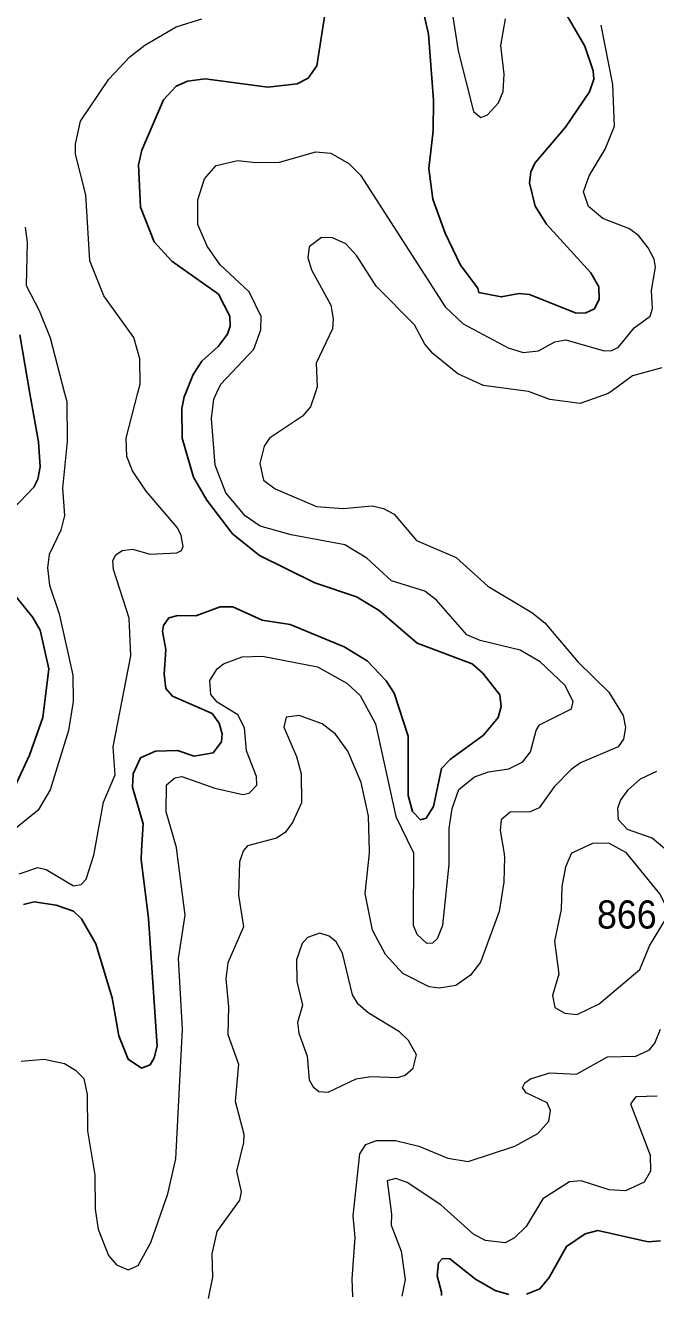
# Model space of a CAD drawing. Extents: x 473.9 to 500, y 7733.1 to 7760.8.
# Drawn here: x 496.397 to 498.186, y 7739.801 to 7743.401 of the extents above; entities that cross this region are included whole.
import ezdxf

# ---------------------------------------------------------------- set-up
doc = ezdxf.new("R2010")
doc.units = 0
doc.header["$LTSCALE"] = 0.032
doc.layers.add('1', color=7, linetype='Continuous', lineweight=25)
doc.layers.add('2', color=7, linetype='Continuous', lineweight=13)
doc.layers.add('21', color=7, linetype='Continuous')

msp = doc.modelspace()

# ---------------------------------------------------------------- linework, layer by layer
at = {"layer": '1'}
for points in [[(497.8918, 7743.5046), (497.9852, 7743.3428), (498.0087, 7743.272), (498.0104, 7743.249), (497.9988, 7743.213), (497.9304, 7743.112)], [(497.2476, 7743.4377), (497.2241, 7743.2861), (497.1996, 7743.2511), (497.1683, 7743.2354), (497.0852, 7743.2257), (496.9077, 7743.2496), (496.8576, 7743.2432), (496.8254, 7743.2288), (496.7893, 7743.1899), (496.7276, 7743.0471), (496.7185, 7743.0052), (496.7237, 7742.885), (496.7626, 7742.7874), (496.8129, 7742.732), (496.9455, 7742.6383), (496.977, 7742.5762), (496.9783, 7742.5475), (496.9708, 7742.5246), (496.9447, 7742.4894), (496.8978, 7742.448), (496.8729, 7742.4108), (496.8522, 7742.3587), (496.8477, 7742.3473), (496.8415, 7742.3136), (496.8423, 7742.2294), (496.8747, 7742.1189), (496.9117, 7742.0536), (496.9851, 7741.958), (497.062, 7741.8961), (497.2183, 7741.8191), (497.3373, 7741.7796), (497.401, 7741.7405), (497.5088, 7741.6474), (497.6658, 7741.5886), (497.6961, 7741.5621), (497.7437, 7741.5013), (497.7474, 7741.4682), (497.7392, 7741.4364), (497.6973, 7741.3867), (497.6039, 7741.3185), (497.578, 7741.2922), (497.5554, 7741.1843), (497.5345, 7741.1512), (497.5186, 7741.1466), (497.4959, 7741.17), (497.4833, 7741.215), (497.4838, 7741.3836), (497.4438, 7741.5054), (497.4209, 7741.5409), (497.3669, 7741.5977), (497.3019, 7741.6369), (497.1486, 7741.7011), (497.0688, 7741.7134), (496.9862, 7741.7509), (496.9502, 7741.7508), (496.8806, 7741.7256), (496.8302, 7741.7261), (496.8045, 7741.7196), (496.7895, 7741.6977), (496.786, 7741.6806), (496.7955, 7741.6296), (496.7908, 7741.5599), (496.7956, 7741.5192), (496.8145, 7741.4968), (496.9275, 7741.4483)], [(497.9304, 7743.112), (497.8433, 7743.0101), (497.8318, 7742.9855), (497.828, 7742.9546), (497.8444, 7742.8884), (497.8766, 7742.8367), (498.002, 7742.6985), (498.0251, 7742.6594), (498.0263, 7742.6244), (498.0123, 7742.5966), (497.9883, 7742.5854), (497.9604, 7742.5847), (497.8283, 7742.6375), (497.7989, 7742.6402), (497.7479, 7742.6307), (497.6842, 7742.6428), (497.6814, 7742.6552), (497.6325, 7742.7203), (497.5887, 7742.8112), (497.5535, 7742.9084), (497.5426, 7742.9948), (497.5547, 7743.1017), (497.5554, 7743.1891), (497.5413, 7743.3765), (497.525, 7743.4473)], [(496.3185, 7741.9843), (496.4214, 7742.0908), (496.4323, 7742.1137), (496.4386, 7742.1484), (496.4342, 7742.2195), (496.4101, 7742.3567), (496.3808, 7742.5231)], [(496.3542, 7741.2116), (496.4091, 7741.3295), (496.4461, 7741.4363), (496.4636, 7741.5749), (496.4394, 7741.6842), (496.4177, 7741.7208), (496.3434, 7741.8135)], [(496.9275, 7741.4483), (496.9472, 7741.4205), (496.9555, 7741.3903), (496.9534, 7741.3672), (496.9302, 7741.3365), (496.8757, 7741.3265), (496.8289, 7741.3426), (496.7661, 7741.3416), (496.7241, 7741.3223), (496.7034, 7741.2771), (496.701, 7741.2392), (496.7311, 7741.135), (496.7271, 7741.0601), (496.7257, 7741.0333), (496.7465, 7740.8658), (496.7707, 7740.504), (496.7628, 7740.4708), (496.751, 7740.4509), (496.7269, 7740.4414), (496.6885, 7740.4672), (496.6625, 7740.5333), (496.6435, 7740.6413), (496.5967, 7740.794), (496.5559, 7740.8652), (496.534, 7740.8867), (496.4844, 7740.9044), (496.4217, 7740.9131), (496.3913, 7740.9056)], [(498.1997, 7739.9512), (498.1651, 7739.9485), (498.0218, 7739.9804), (497.9859, 7739.9712), (497.9329, 7739.9352), (497.8837, 7739.8469), (497.8576, 7739.815), (497.8194, 7739.7995)], [(497.7699, 7739.7987), (497.7311, 7739.81), (497.6752, 7739.8425), (497.6015, 7739.9004), (497.5807, 7739.9007), (497.5698, 7739.8885), (497.5657, 7739.8517), (497.5779, 7739.8059), (497.5781, 7739.7957)]]:
    msp.add_lwpolyline(points, dxfattribs=at)
at = {"layer": '2'}
for points in [[(497.5986, 7743.505), (497.6257, 7743.3291), (497.6689, 7743.1573), (497.69, 7743.1399), (497.7088, 7743.1472), (497.7398, 7743.1812), (497.7532, 7743.2141), (497.7564, 7743.2624), (497.7467, 7743.3444), (497.7597, 7743.4199)], [(496.4324, 7741.0112), (496.4556, 7741.0056), (496.5338, 7740.9585), (496.555, 7740.9631), (496.5696, 7740.9776), (496.5914, 7741.046), (496.5941, 7741.0607), (496.6186, 7741.1963), (496.6515, 7741.2737), (496.6462, 7741.3533), (496.6959, 7741.612), (496.6914, 7741.719), (496.6469, 7741.8567), (496.6454, 7741.882), (496.6542, 7741.8986), (496.6713, 7741.9104), (496.7015, 7741.9141), (496.7515, 7741.9007), (496.8272, 7741.9039), (496.8404, 7741.9111), (496.8446, 7741.9224), (496.8394, 7741.9532), (496.8286, 7741.9747), (496.7399, 7742.079), (496.7007, 7742.137), (496.6848, 7742.1774), (496.6834, 7742.2295), (496.7161, 7742.3581), (496.7224, 7742.3828), (496.7217, 7742.4549), (496.7047, 7742.5156), (496.6193, 7742.6336), (496.5797, 7742.7332), (496.5689, 7742.9204), (496.5395, 7743.0354), (496.5392, 7743.064), (496.5538, 7743.1297), (496.6341, 7743.2489), (496.6939, 7743.312), (496.7362, 7743.3454), (496.8253, 7743.3976), (496.8983, 7743.4202)], [(498.0405, 7742.4772), (498.0623, 7742.4783), (498.0811, 7742.4876), (498.1256, 7742.5432), (498.1709, 7742.5763), (498.1777, 7742.5977), (498.1746, 7742.6486), (498.1857, 7742.715), (498.1817, 7742.7375), (498.1654, 7742.7702), (498.1384, 7742.8042), (498.1124, 7742.8241), (498.0363, 7742.8527), (497.9952, 7742.8871), (497.9818, 7742.9288), (497.9971, 7742.9745), (498.0431, 7743.0504), (498.0693, 7743.1157), (498.0649, 7743.2335), (498.0319, 7743.4018)], [(496.6886, 7739.8689), (496.717, 7739.8811), (496.7532, 7739.9466), (496.801, 7740.0845), (496.8245, 7740.184), (496.8431, 7740.5516), (496.8319, 7740.7528), (496.8503, 7740.876), (496.827, 7741.0596), (496.826, 7741.0674), (496.7963, 7741.1693), (496.7975, 7741.2454), (496.8216, 7741.2658), (496.8415, 7741.2694), (496.9348, 7741.2365), (497.014, 7741.218), (497.0327, 7741.2221), (497.0538, 7741.2443), (497.0535, 7741.2693), (497.0243, 7741.3417), (497.0186, 7741.4075), (497.0004, 7741.4447), (496.9412, 7741.4801), (496.9237, 7741.5021), (496.9205, 7741.5415), (496.9411, 7741.5748), (496.9599, 7741.5893), (497.0124, 7741.6092), (497.0698, 7741.6111), (497.2262, 7741.5809), (497.3095, 7741.5342), (497.3475, 7741.499), (497.3908, 7741.4185), (497.4487, 7741.1554), (497.4973, 7741.0565), (497.4988, 7741.0535), (497.4982, 7740.8471), (497.5081, 7740.8217), (497.5359, 7740.7959), (497.5536, 7740.7968), (497.5665, 7740.8093), (497.5825, 7740.8476), (497.6004, 7741.0197), (497.6002, 7741.056), (497.5997, 7741.1215), (497.6086, 7741.1784), (497.6275, 7741.2319), (497.6721, 7741.268), (497.7119, 7741.282), (497.7699, 7741.2906), (497.809, 7741.3104), (497.8307, 7741.3395), (497.8466, 7741.4), (497.8563, 7741.4156), (497.9476, 7741.4617), (497.9522, 7741.4824), (497.9288, 7741.5288), (497.8583, 7741.5951), (497.8015, 7741.628), (497.6876, 7741.6554), (497.6506, 7741.671), (497.5642, 7741.7695), (497.531, 7741.7957), (497.4364, 7741.8243), (497.3659, 7741.8889), (497.3035, 7741.9268), (497.1519, 7741.9549), (497.0638, 7741.98), (497.0208, 7742.009), (496.9657, 7742.0746), (496.9358, 7742.1533), (496.9251, 7742.2853), (496.9322, 7742.3405), (496.9407, 7742.3591), (496.9517, 7742.3832), (497.0458, 7742.4821), (497.0656, 7742.5376), (497.0659, 7742.575), (497.0324, 7742.6454), (496.9504, 7742.7221), (496.9128, 7742.7751), (496.887, 7742.8365), (496.8866, 7742.9063), (496.9055, 7742.9654), (496.9386, 7743.0039), (497, 7743.018), (497.051, 7743.0118), (497.118, 7743.0134), (497.2215, 7743.0423), (497.2645, 7743.0383), (497.3155, 7743.0097), (497.3482, 7742.9764), (497.5889, 7742.6021), (497.6401, 7742.554), (497.7678, 7742.4859), (497.8105, 7742.4724), (497.8535, 7742.4772), (497.8996, 7742.5035), (497.9317, 7742.5092), (498.0405, 7742.4772)], [(496.3961, 7742.8284), (496.4025, 7742.7857), (496.3992, 7742.6632), (496.4364, 7742.5923), (496.4671, 7742.5145), (496.5083, 7742.3571), (496.5144, 7742.3337), (496.5158, 7742.2198), (496.5022, 7742.0875), (496.5085, 7742.0097), (496.4973, 7741.9689), (496.4647, 7741.8996), (496.4595, 7741.8615), (496.4658, 7741.8119), (496.4928, 7741.7314), (496.5321, 7741.5572), (496.5327, 7741.4823), (496.5198, 7741.3998), (496.4669, 7741.2314), (496.4334, 7741.1741), (496.3293, 7741.0899)], [(498.2034, 7742.4289), (498.1209, 7742.4061), (498.0631, 7742.3643), (498.0518, 7742.3561), (497.9719, 7742.3276), (497.8856, 7742.3394), (497.8256, 7742.3621), (497.8176, 7742.3631), (497.698, 7742.3787), (497.625, 7742.4124), (497.5535, 7742.4703), (497.5312, 7742.4962), (497.5019, 7742.5515), (497.3926, 7742.6615), (497.3383, 7742.7472), (497.3064, 7742.7812), (497.2692, 7742.7986), (497.2373, 7742.7994), (497.2027, 7742.773), (497.1985, 7742.7414), (497.2095, 7742.7076), (497.2637, 7742.6068), (497.2708, 7742.5687), (497.2687, 7742.5398), (497.2221, 7742.4428), (497.2257, 7742.3753), (497.2207, 7742.3604), (497.2066, 7742.3184), (497.1836, 7742.2919), (497.09, 7742.2293), (497.0752, 7742.2068), (497.0627, 7742.1576), (497.0734, 7742.1107), (497.106, 7742.0856), (497.2236, 7742.0354), (497.2992, 7742.0301), (497.3817, 7742.0379), (497.4139, 7742.0302), (497.4439, 7742.0142), (497.5069, 7741.9392), (497.6197, 7741.8907), (497.7098, 7741.8091), (497.8346, 7741.7351), (497.8712, 7741.7053), (497.9649, 7741.595), (498.0534, 7741.5085), (498.0939, 7741.442), (498.1011, 7741.4083), (498.0949, 7741.375), (498.0797, 7741.3531), (497.9731, 7741.3077), (497.9466, 7741.2893), (497.8978, 7741.2397), (497.8558, 7741.1804), (497.8304, 7741.169), (497.7732, 7741.1683), (497.7474, 7741.1465), (497.7448, 7741.1161), (497.7548, 7741.0553), (497.7571, 7741.0411), (497.7548, 7740.9693), (497.7418, 7740.886), (497.6888, 7740.7419), (497.6603, 7740.7054), (497.6191, 7740.6764), (497.572, 7740.6681), (497.5437, 7740.6723), (497.4682, 7740.7102), (497.4197, 7740.7644), (497.3822, 7740.8326), (497.3617, 7740.9371), (497.3737, 7741.0518), (497.3735, 7741.0571), (497.3706, 7741.1563), (497.3499, 7741.2521), (497.3128, 7741.3413), (497.2772, 7741.3892), (497.2392, 7741.4187), (497.1738, 7741.4423), (497.1375, 7741.4374), (497.1307, 7741.4088), (497.1668, 7741.3263), (497.1799, 7741.2769), (497.1807, 7741.1944), (497.1556, 7741.1387)], [(498.2248, 7741.0532), (498.1767, 7741.0939), (498.106, 7741.1188), (498.0808, 7741.1466), (498.0787, 7741.1794), (498.0863, 7741.2008), (498.1085, 7741.2316), (498.1428, 7741.2625), (498.1895, 7741.2841)], [(497.1556, 7741.1387), (497.1341, 7741.1103), (497.1095, 7741.094), (497.0278, 7741.0725), (497.0166, 7741.0587), (497.0151, 7741.0569), (497.0045, 7741.0272), (497.0023, 7740.9322), (497.016, 7740.8423), (496.9718, 7740.7404), (496.966, 7740.6948), (496.9733, 7740.6155), (496.9718, 7740.5371), (497.0022, 7740.4525), (496.9928, 7740.3475), (497.0167, 7740.2542), (497.0165, 7740.2301), (496.9967, 7740.1492), (497.0094, 7740.0906), (497.0053, 7740.0668), (496.9401, 7739.9772), (496.9265, 7739.9143), (496.9283, 7739.8479), (496.9161, 7739.7874)], [(496.3789, 7740.9931), (496.4324, 7741.0112)], [(497.3265, 7739.7925), (497.3246, 7739.8436), (497.3336, 7739.9605), (497.328, 7740.0224), (497.3466, 7740.1985), (497.3632, 7740.2244), (497.3936, 7740.2355), (497.4476, 7740.2364), (497.5136, 7740.2202), (497.5967, 7740.1858), (497.654, 7740.176), (497.7869, 7740.2196), (497.8514, 7740.2554), (497.8829, 7740.2906), (497.8882, 7740.3207), (497.8781, 7740.3433), (497.819, 7740.3715), (497.8081, 7740.3862), (497.8145, 7740.3997), (497.8309, 7740.411), (497.8859, 7740.4283), (497.9612, 7740.4242), (498.0499, 7740.4734), (498.13, 7740.475), (498.1684, 7740.4938), (498.1843, 7740.5126), (498.2, 7740.5517)], [(496.3854, 7740.4615), (496.4501, 7740.467), (496.5082, 7740.4544), (496.5397, 7740.4356), (496.5629, 7740.4116), (496.5728, 7740.3663), (496.573, 7740.2634), (496.5939, 7740.1384), (496.5947, 7740.0414), (496.6036, 7739.9841), (496.6325, 7739.9091), (496.6555, 7739.883), (496.6886, 7739.8689)], [(498.1905, 7740.3618), (498.1302, 7740.3601), (498.1151, 7740.3404), (498.1702, 7740.1948), (498.172, 7740.1493), (498.1537, 7740.1173), (498.1008, 7740.0932), (498.054, 7740.096), (497.9751, 7740.1213), (497.9419, 7740.119), (497.8658, 7740.0706), (497.819, 7739.9921), (497.7857, 7739.9595), (497.7587, 7739.9456), (497.7034, 7739.952), (497.6699, 7739.9695), (497.5763, 7740.0537), (497.4806, 7740.1172), (497.4483, 7740.1284), (497.4239, 7740.1217), (497.4363, 7740.027), (497.435, 7739.9955), (497.4634, 7739.9215), (497.475, 7739.8415), (497.4657, 7739.7943)]]:
    msp.add_lwpolyline(points, dxfattribs=at)
for points in [[(498.1687, 7740.7886), (498.2144, 7740.8633), (498.2155, 7740.9032), (498.1985, 7740.9365), (498.1024, 7741.0534), (498.1018, 7741.0537), (498.0533, 7741.0802), (498.007, 7741.0795), (497.9539, 7741.0544), (497.9478, 7741.0515), (497.93, 7741.0132), (497.9197, 7740.957), (497.9181, 7740.8921), (497.8994, 7740.8021), (497.9115, 7740.7082), (497.8936, 7740.6477), (497.9003, 7740.6137), (497.9286, 7740.5973), (497.9632, 7740.5933), (498.0259, 7740.6238), (498.1409, 7740.7218)], [(497.3697, 7740.5984), (497.3416, 7740.6231), (497.3257, 7740.6498), (497.2973, 7740.7677), (497.2792, 7740.7995), (497.2598, 7740.8161), (497.2325, 7740.8248), (497.1977, 7740.8118), (497.1829, 7740.7953), (497.1664, 7740.749), (497.168, 7740.687), (497.1838, 7740.6204), (497.1697, 7740.5707), (497.1733, 7740.5405), (497.1966, 7740.4755), (497.203, 7740.4086), (497.2136, 7740.3884), (497.2305, 7740.3751), (497.2569, 7740.373), (497.3362, 7740.4114), (497.378, 7740.4178), (497.454, 7740.4144), (497.4754, 7740.4215), (497.498, 7740.4413), (497.5071, 7740.4794), (497.4842, 7740.5198), (497.4587, 7740.5441)]]:
    msp.add_lwpolyline(points, close=True, dxfattribs=at)

# ---------------------------------------------------------------- texts
at = {"layer": '21', "width": 0.95}
msp.add_text('866', height=0.08, dxfattribs=at).set_placement((498.0196, 7740.8376))

doc.saveas('drawing.dxf')
